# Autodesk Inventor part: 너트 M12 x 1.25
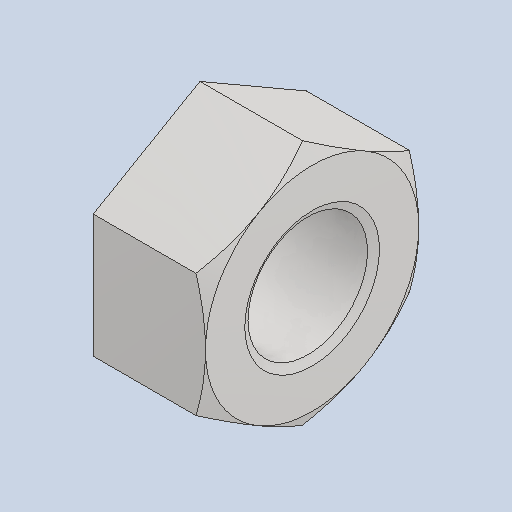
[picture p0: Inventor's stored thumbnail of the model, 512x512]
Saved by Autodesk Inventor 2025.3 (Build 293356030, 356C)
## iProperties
Created: 2025-08
Part Number: 너트 M12 x 1.25
Material: 스테인리스강
Description: 6각 너트
Document SubType Name: Modeling
Designer: infra011
Density: 8.08 g/cm^3
Appearance: 기본값
Author: jhkim
Sending System: Autodesk Inventor 2026
Preprocessor: ST-DEVELOPER v20.1
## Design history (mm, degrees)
feature "Solid1"
node "솔리드1"
